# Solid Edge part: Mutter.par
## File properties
Sűrűség: 0,000 kg/m^3
Pontosság: 0,990
Author: ahadarics
Last saved by: psaghy
Revision: 77
Username: ahadarics
Dokumentum tartalom típus: 0
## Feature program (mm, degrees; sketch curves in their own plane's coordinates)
base feature "unnamed BaseFeature 1"
sketch for "Furat_1" plane through (0, 0, 0) normal (-1, 0, 0) x-axis (0, -1, 0)
  hole centre (0, 0) bore radius 19.9175
hole "Furat_1" through  StartChamferOffset = 0.92 mm; StartChamferAngle = 45 deg
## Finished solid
Body 1: solid body, 23 faces, 47 edges, 26 vertices.
  Faces by surface: cone 14, plane 8, cylinder 1
  Edges by curve: spline 24, circle 16, line 7
Bounding box of the edges (mm): 16.000 x 75.055 x 65.000, from (0, -37.5278, -32.5) to (16, 37.5278, 32.5).
Cylindrical faces by radius (mm): R19.9175 x1
Conical faces (half-angle, radius in mm at the cone's reference point): 45 deg R20.8375 x1, 60 deg R20.1881 x1, 60 deg R35.0139 x12
Planar faces by outward normal: +x 1, +z 1, -x 1, -z 1, oblique 4
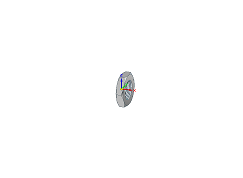
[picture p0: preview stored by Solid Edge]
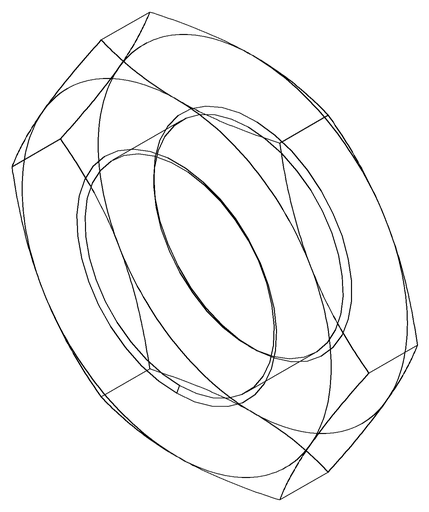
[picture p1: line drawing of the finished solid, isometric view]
